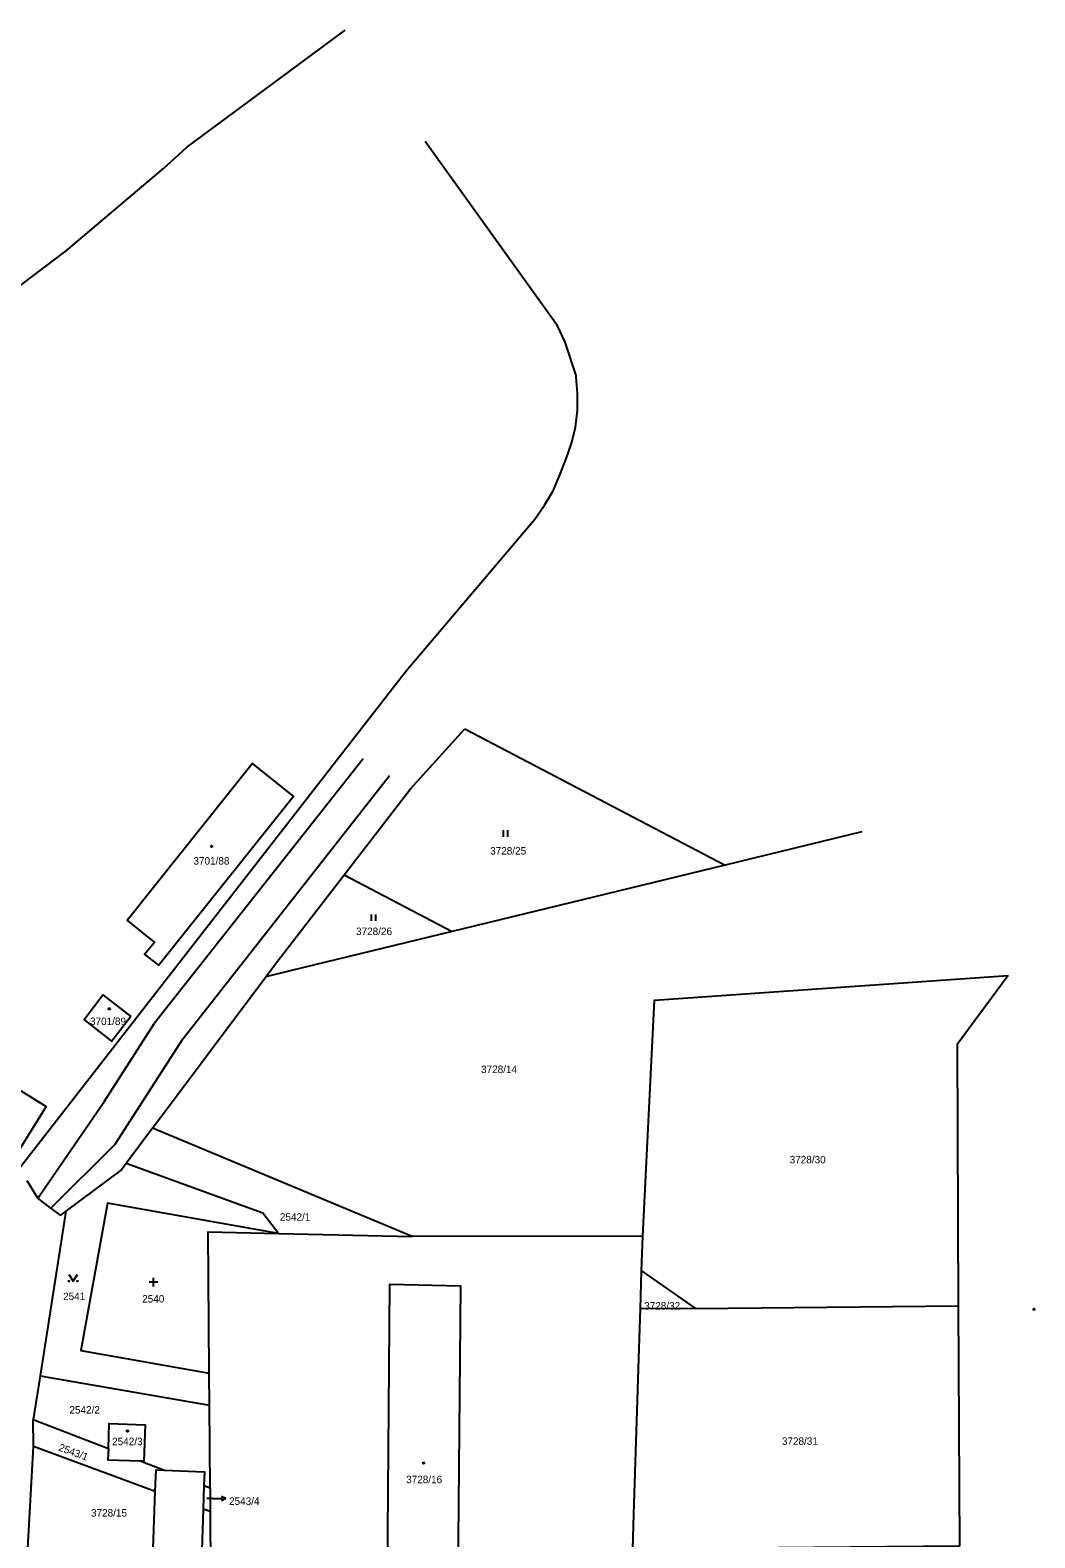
# Model space of a CAD drawing. Extents: x -527335 to -526256, y -1079142 to -1077809.
# Drawn here: x -526590.6 to -526361.2, y -1078153 to -1077809 of the extents above; entities that cross this region are included whole.
import ezdxf

# ---------------------------------------------------------------- set-up
doc = ezdxf.new("R2010")
doc.units = 0
for name, color, linetype in [('Vrstva 1', 7, 'Continuous'), ('Vrstva 2', 7, 'Continuous'), ('Vrstva 3', 7, 'Continuous'), ('Vrstva 4', 7, 'Continuous'), ('Vrstva 5', 7, 'Continuous'), ('Vrstva 7', 7, 'Continuous')]:
    doc.layers.add(name, color=color, linetype=linetype)

msp = doc.modelspace()

# ---------------------------------------------------------------- linework, layer by layer
at = {"layer": 'Vrstva 1'}
for p, q in [((-526491.37, -1077968.39), (-526431.97, -1077999.5)), ((-526400.75, -1077991.92), (-526431.97, -1077999.5)), ((-526431.97, -1077999.5), (-526494.24, -1078014.63)), ((-526518.91, -1078001.71), (-526494.24, -1078014.63)), ((-526562.63, -1078059.54), (-526536.8, -1078024.97)), ((-526562.63, -1078059.54), (-526568.68, -1078067.62)), ((-526503.4, -1078084.27), (-526562.63, -1078059.54)), ((-526582.48, -1078078.47), (-526588.33, -1078116.06)), ((-526533.93, -1078083.55), (-526503.4, -1078084.27)), ((-526450.76, -1078084.21), (-526503.4, -1078084.27)), ((-526451.02, -1078092.08), (-526450.76, -1078084.21)), ((-526451.3, -1078100.77), (-526451.02, -1078092.08)), ((-526451.02, -1078092.08), (-526438.72, -1078100.65)), ((-526438.72, -1078100.65), (-526451.3, -1078100.77)), ((-526438.72, -1078100.65), (-526378.72, -1078100.08)), ((-526378.72, -1078100.08), (-526378.46, -1078154.92)), ((-526588.33, -1078116.06), (-526589.88, -1078126.02)), ((-526588.33, -1078116.06), (-526549.66, -1078122.71)), ((-526549.66, -1078122.71), (-526549.71, -1078115.43)), ((-526549.53, -1078141.61), (-526549.66, -1078122.71)), ((-526589.88, -1078126.02), (-526572.73, -1078132.64)), ((-526589.8, -1078132.18), (-526589.88, -1078126.02)), ((-526593.02, -1078188.05), (-526589.8, -1078132.18)), ((-526562.04, -1078142.41), (-526589.8, -1078132.18)), ((-526565.46, -1078135.45), (-526559.9, -1078137.6)), ((-526562.53, -1078155.46), (-526562.04, -1078142.41)), ((-526550.93, -1078141.07), (-526551.11, -1078146.44)), ((-526550.93, -1078141.07), (-526549.53, -1078141.61)), ((-526549.53, -1078141.61), (-526549.5, -1078147.03)), ((-526549.5, -1078147.03), (-526551.11, -1078146.44)), ((-526549.5, -1078147.03), (-526549.12, -1078203.3))]:
    msp.add_line(p, q, dxfattribs=at)
for points in [[(-526673.11, -1077936.27), (-526628.3, -1077898.33), (-526617.18, -1077887.63), (-526607.04, -1077877.88), (-526582.34, -1077859.35), (-526560.13, -1077840.53), (-526554.92, -1077835.73), (-526518.72, -1077808.97)], [(-526593.1, -1078068.73), (-526504.73, -1077955.15), (-526475.36, -1077920.58), (-526473.2, -1077917.35), (-526471.14, -1077913.91), (-526469.68, -1077910.44), (-526468.25, -1077906.77), (-526467.03, -1077903.29), (-526466.08, -1077899.56), (-526465.62, -1077895.73), (-526465.66, -1077891.83), (-526465.95, -1077888.19), (-526465.98, -1077887.79), (-526468.46, -1077880.16), (-526470.2, -1077876.45), (-526500.42, -1077834.41)], [(-526518.91, -1078001.71), (-526503.79, -1077982.12), (-526491.37, -1077968.39)], [(-526568.47, -1078012.07), (-526539.94, -1077976.3), (-526530.5, -1077983.86), (-526561.22, -1078022.3), (-526564.51, -1078019.83), (-526562.24, -1078017.08), (-526568.47, -1078012.07)], [(-526536.8, -1078024.97), (-526534.6, -1078022.04), (-526518.91, -1078001.71)], [(-526494.24, -1078014.63), (-526531.25, -1078023.62), (-526536.8, -1078024.97)], [(-526450.76, -1078084.21), (-526448.05, -1078030.31), (-526367.31, -1078024.69)], [(-526367.31, -1078024.69), (-526379.01, -1078040.47), (-526378.72, -1078100.08)], [(-526567.6, -1078034.05), (-526571.98, -1078039.64), (-526578.28, -1078034.7), (-526573.98, -1078029.08), (-526567.6, -1078034.05)], [(-526586.95, -1078054.58), (-526593.21, -1078064.63), (-526605.07, -1078057.53), (-526598.91, -1078047.22), (-526586.95, -1078054.58)], [(-526568.68, -1078067.62), (-526569.7, -1078068.99), (-526582.48, -1078078.47)], [(-526533.93, -1078083.55), (-526537.44, -1078078.89), (-526568.68, -1078067.62)], [(-526582.48, -1078078.47), (-526583.67, -1078079.36), (-526585.84, -1078077.75), (-526588.82, -1078075.54), (-526591.31, -1078071.57)], [(-526533.93, -1078083.55), (-526572.91, -1078076.63), (-526579.03, -1078110.28), (-526549.71, -1078115.43)], [(-526549.71, -1078115.43), (-526549.71, -1078114.89), (-526549.92, -1078083.17), (-526537.12, -1078083.47), (-526533.93, -1078083.55)], [(-526508.9, -1078161.24), (-526509.01, -1078161.24), (-526508.5, -1078095.15), (-526492.37, -1078095.48), (-526492.95, -1078161.84), (-526493.06, -1078161.83), (-526493.24, -1078180.39), (-526509.08, -1078180.27), (-526508.9, -1078161.24)], [(-526378.46, -1078154.92), (-526453.05, -1078155.62), (-526452.8, -1078147.63), (-526451.59, -1078109.7), (-526451.3, -1078100.77)], [(-526572.73, -1078132.64), (-526572.52, -1078126.93), (-526564.31, -1078127.19), (-526564.63, -1078135.48), (-526565.46, -1078135.45)], [(-526572.73, -1078132.64), (-526572.83, -1078135.22), (-526565.46, -1078135.45)], [(-526562.04, -1078142.41), (-526561.85, -1078137.53), (-526559.9, -1078137.6)], [(-526559.9, -1078137.6), (-526550.83, -1078137.95), (-526550.93, -1078141.07)], [(-526551.11, -1078146.44), (-526551.42, -1078155.85), (-526552.45, -1078185.98), (-526562.44, -1078185.64), (-526563.48, -1078185.6), (-526563.34, -1078181)]]:
    msp.add_lwpolyline(points, dxfattribs=at)
at = {"layer": 'Vrstva 3'}
for p, q in [((-526482.54, -1077993.03), (-526482.54, -1077991.53)), ((-526481.54, -1077993.03), (-526481.54, -1077991.53)), ((-526512.68, -1078012.24), (-526512.68, -1078010.74)), ((-526511.68, -1078012.24), (-526511.68, -1078010.74)), ((-526561.44, -1078094.66), (-526563.44, -1078094.66)), ((-526562.44, -1078095.66), (-526562.44, -1078093.66))]:
    msp.add_line(p, q, dxfattribs=at)
msp.add_lwpolyline([(-526581.76, -1078092.95), (-526580.76, -1078094.45), (-526579.76, -1078092.95)], dxfattribs=at)
for centre in [(-526581.76, -1078094.45), (-526579.76, -1078094.45)]:
    msp.add_circle(centre, 0.1, dxfattribs=at)
at = {"layer": 'Vrstva 4'}
for p, q in [((-526514.58, -1077975.22), (-526562.2, -1078035.6)), ((-526555.65, -1078039.07), (-526508.57, -1077979.06)), ((-526573.6, -1078053.37), (-526562.2, -1078035.6)), ((-526571.16, -1078063.16), (-526555.65, -1078039.07)), ((-526588.82, -1078075.54), (-526573.6, -1078053.37)), ((-526585.84, -1078077.75), (-526571.16, -1078063.16))]:
    msp.add_line(p, q, dxfattribs=at)
at = {"layer": 'Vrstva 5'}
for centre in [(-526549.16, -1077995.2), (-526572.5, -1078032.3), (-526361.42, -1078100.86), (-526568.38, -1078128.62), (-526500.79, -1078135.96)]:
    msp.add_circle(centre, 0.175, dxfattribs=at)
at = {"layer": 'Vrstva 7'}
for p, q in [((-526548.94, -1078144.07), (-526550.26, -1078144.07)), ((-526548.94, -1078144.07), (-526545.94, -1078144.07)), ((-526545.94, -1078144.07), (-526546.94, -1078143.57)), ((-526545.94, -1078144.07), (-526546.94, -1078144.57))]:
    msp.add_line(p, q, dxfattribs=at)

# ---------------------------------------------------------------- texts
at = {"layer": 'Vrstva 2'}
for s, p in [('3728/25', (-526485.58, -1077997.09)), ('3701/88', (-526553.32, -1077999.38)), ('3728/26', (-526516.2, -1078015.46)), ('3701/89', (-526576.93, -1078035.99)), ('3728/14', (-526487.66, -1078046.94)), ('3728/30', (-526417.21, -1078067.55)), ('2542/1', (-526533.59, -1078080.64)), ('2541', (-526583.08, -1078098.76)), ('2540', (-526565.02, -1078099.32)), ('3728/32', (-526450.43, -1078100.92)), ('2542/2', (-526581.62, -1078124.66)), ('2542/3', (-526571.88, -1078131.87)), ('3728/31', (-526418.99, -1078131.79)), ('3728/16', (-526504.76, -1078140.54)), ('2543/4', (-526545.19, -1078145.49)), ('3728/15', (-526576.7, -1078148.17))]:
    msp.add_text(s, height=1.7, dxfattribs=at).set_placement(p)
msp.add_text('2543/1', height=1.7, rotation=340, dxfattribs=at).set_placement((-526584.26, -1078133.06))

doc.saveas('drawing.dxf')
